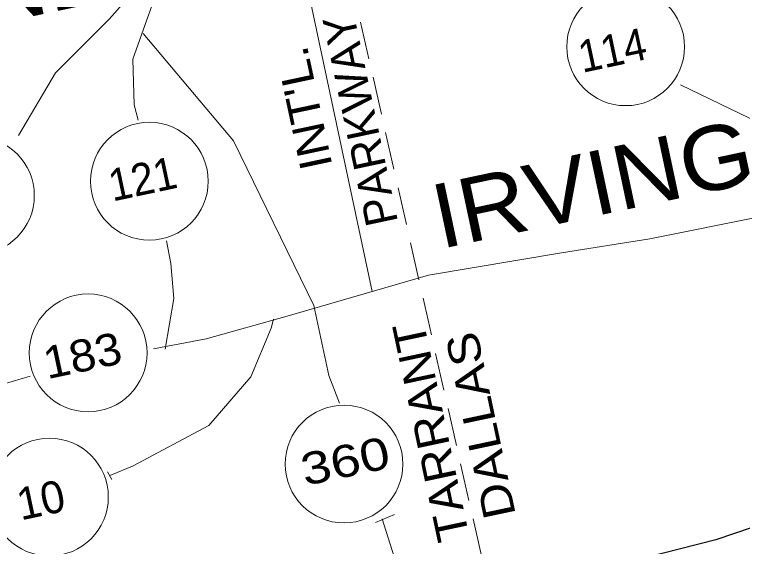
# Model space of a CAD drawing. Extents: x 2357218 to 2371708, y 6973728 to 6980157.
# Drawn here: x 2371493.9 to 2371609.7, y 6977662.2 to 6977746.8 of the extents above; entities that cross this region are included whole.
import ezdxf

# ---------------------------------------------------------------- set-up
doc = ezdxf.new("R2010")
doc.units = 0
doc.header["$LTSCALE"] = 2
doc.linetypes.add('MEDIUM_DASHED', pattern=[4.5, 3, -1.5])
doc.layers.add('62', color=7, linetype='Continuous', lineweight=13)
doc.layers.add('63', color=7, linetype='Continuous', lineweight=13)

msp = doc.modelspace()

# ---------------------------------------------------------------- linework, layer by layer
at = {"layer": '62', "linetype": 'MEDIUM_DASHED'}
msp.add_line((2371537.006, 6977798.267), (2371599.077, 6977524.204), dxfattribs=at)
at = {"layer": '62'}
for p, q in [((2371550.77, 6977702.778), (2371536.566, 6977769.602)), ((2371500.416, 6977737.511), (2371494.527, 6977727.54)), ((2371619.865, 6977725.887), (2371599.831, 6977735.614)), ((2371512.926, 6977732.44), (2371513.583, 6977730.002)), ((2371518.746, 6977707.223), (2371518.055, 6977710.804)), ((2371541.521, 6977700.514), (2371543.881, 6977689.421)), ((2371534.709, 6977696.949), (2371535.099, 6977698.366)), ((2371524.394, 6977695.264), (2371516.02, 6977693.645)), ((2371492.088, 6977688.052), (2371496.395, 6977689.313)), ((2371543.881, 6977689.421), (2371545.577, 6977684.998)), ((2371512.664, 6977675.013), (2371509.322, 6977673.634)), ((2371508.672, 6977674.095), (2371509.393, 6977672.868)), ((2371509.001, 6977673.519), (2371509.322, 6977673.634)), ((2371551.31, 6977666.04), (2371554.305, 6977667.32)), ((2371556.106, 6977654.73), (2371552.361, 6977666.609))]:
    msp.add_line(p, q, dxfattribs=at)
for points in [[(2371516.467, 6977754.633), (2371509.005, 6977746.124), (2371500.416, 6977737.511)], [(2371512.926, 6977732.44), (2371512.737, 6977739.718), (2371516.072, 6977749.143)], [(2371541.521, 6977700.514), (2371528.745, 6977726.738), (2371514.339, 6977743.761)], [(2371524.394, 6977695.264), (2371537.271, 6977698.852), (2371559.74, 6977705.374), (2371580.871, 6977708.9), (2371594.951, 6977711.158), (2371612.626, 6977714.706), (2371622.215, 6977719.277), (2371632.346, 6977728.746), (2371643.913, 6977738.084), (2371647.591, 6977740.041)], [(2371517.843, 6977693.618), (2371519.238, 6977701.666), (2371518.746, 6977707.223)], [(2371512.664, 6977675.013), (2371524.821, 6977681.459), (2371531.481, 6977689.201), (2371534.709, 6977696.949)]]:
    msp.add_lwpolyline(points, dxfattribs=at)
at = {"layer": '62', "lineweight": 25}
msp.add_lwpolyline([(2371659.938, 6977681.952), (2371647.349, 6977677.965), (2371628.369, 6977671.057), (2371605.423, 6977663.305), (2371580.264, 6977656.875), (2371551.849, 6977650.836), (2371520.802, 6977643.338), (2371503.25, 6977638.459)], dxfattribs=at)
at = {"layer": '62'}
for centre in [(2371591.092, 6977741.673), (2371515.35, 6977720.296), (2371487.691, 6977718.022), (2371505.61, 6977693.006), (2371546.31, 6977675.334), (2371499.456, 6977670.084)]:
    msp.add_circle(centre, 9.364, dxfattribs=at)
at = {"layer": '63', "linetype": 'MEDIUM_DASHED'}
msp.add_line((2371537.006, 6977798.267), (2371599.077, 6977524.204), dxfattribs=at)
at = {"layer": '63'}
for p, q in [((2371550.77, 6977702.778), (2371536.566, 6977769.602)), ((2371500.416, 6977737.511), (2371494.527, 6977727.54)), ((2371619.865, 6977725.887), (2371599.831, 6977735.614)), ((2371512.926, 6977732.44), (2371513.583, 6977730.002)), ((2371518.746, 6977707.223), (2371518.055, 6977710.804)), ((2371541.521, 6977700.514), (2371543.881, 6977689.421)), ((2371534.709, 6977696.949), (2371535.099, 6977698.366)), ((2371524.394, 6977695.264), (2371516.02, 6977693.645)), ((2371492.088, 6977688.052), (2371496.395, 6977689.313)), ((2371543.881, 6977689.421), (2371545.577, 6977684.998)), ((2371512.664, 6977675.013), (2371509.322, 6977673.634)), ((2371508.672, 6977674.095), (2371509.393, 6977672.868)), ((2371509.001, 6977673.519), (2371509.322, 6977673.634)), ((2371551.31, 6977666.04), (2371554.305, 6977667.32)), ((2371556.106, 6977654.73), (2371552.361, 6977666.609))]:
    msp.add_line(p, q, dxfattribs=at)
for points in [[(2371516.467, 6977754.633), (2371509.005, 6977746.124), (2371500.416, 6977737.511)], [(2371512.926, 6977732.44), (2371512.737, 6977739.718), (2371516.072, 6977749.143)], [(2371541.521, 6977700.514), (2371528.745, 6977726.738), (2371514.339, 6977743.761)], [(2371524.394, 6977695.264), (2371537.271, 6977698.852), (2371559.74, 6977705.374), (2371580.871, 6977708.9), (2371594.951, 6977711.158), (2371612.626, 6977714.706), (2371622.215, 6977719.277), (2371632.346, 6977728.746), (2371643.913, 6977738.084), (2371647.591, 6977740.041)], [(2371517.843, 6977693.618), (2371519.238, 6977701.666), (2371518.746, 6977707.223)], [(2371512.664, 6977675.013), (2371524.821, 6977681.459), (2371531.481, 6977689.201), (2371534.709, 6977696.949)]]:
    msp.add_lwpolyline(points, dxfattribs=at)
at = {"layer": '63', "lineweight": 25}
msp.add_lwpolyline([(2371659.938, 6977681.952), (2371647.349, 6977677.965), (2371628.369, 6977671.057), (2371605.423, 6977663.305), (2371580.264, 6977656.875), (2371551.849, 6977650.836), (2371520.802, 6977643.338), (2371503.25, 6977638.459)], dxfattribs=at)
at = {"layer": '63'}
for centre in [(2371591.092, 6977741.673), (2371515.35, 6977720.296), (2371487.691, 6977718.022), (2371505.61, 6977693.006), (2371546.31, 6977675.334), (2371499.456, 6977670.084)]:
    msp.add_circle(centre, 9.364, dxfattribs=at)

# ---------------------------------------------------------------- texts
at = {"layer": '62'}
for s, height, rotation, width, p in [('GRAPEVINE', 10.21, 12, 1.05, (2371427.199, 6977731.726)), ('114', 5.099, 12, 0.95, (2371584.199, 6977737.515)), ("INT'L.", 5.099, 102, 1.1, (2371544.481, 6977722.746)), ('IRVING', 10.21, 12, 1.1, (2371561.625, 6977709.503)), ('121', 5.099, 12, 0.95, (2371509.503, 6977717.06)), ('TARRANT', 5.099, 102, 1.1, (2371566.287, 6977663.659)), ('183', 5.099, 12, 1.1, (2371499.104, 6977688.808)), ('DALLAS', 5.099, 102, 1.15, (2371573.641, 6977667.268)), ('360', 5.099, 12, 1.25, (2371540.071, 6977671.841))]:
    msp.add_text(s, height=height, rotation=rotation, dxfattribs=dict(at, width=width)).set_placement(p)
for s, rotation, p in [('PARKWAY', 102, (2371554.914, 6977713.808)), ('10', 12, (2371494.903, 6977666.36))]:
    msp.add_text(s, height=5.099, rotation=rotation, dxfattribs=at).set_placement(p)
at = {"layer": '63'}
for s, height, rotation, width, p in [('GRAPEVINE', 10.21, 12, 1.05, (2371427.199, 6977731.726)), ('114', 5.099, 12, 0.95, (2371584.199, 6977737.515)), ("INT'L.", 5.099, 102, 1.1, (2371544.481, 6977722.746)), ('IRVING', 10.21, 12, 1.1, (2371561.625, 6977709.503)), ('121', 5.099, 12, 0.95, (2371509.503, 6977717.06)), ('TARRANT', 5.099, 102, 1.1, (2371566.287, 6977663.659)), ('183', 5.099, 12, 1.1, (2371499.104, 6977688.808)), ('DALLAS', 5.099, 102, 1.15, (2371573.641, 6977667.268)), ('360', 5.099, 12, 1.25, (2371540.071, 6977671.841))]:
    msp.add_text(s, height=height, rotation=rotation, dxfattribs=dict(at, width=width)).set_placement(p)
for s, rotation, p in [('PARKWAY', 102, (2371554.914, 6977713.808)), ('10', 12, (2371494.903, 6977666.36))]:
    msp.add_text(s, height=5.099, rotation=rotation, dxfattribs=at).set_placement(p)

doc.saveas('drawing.dxf')
